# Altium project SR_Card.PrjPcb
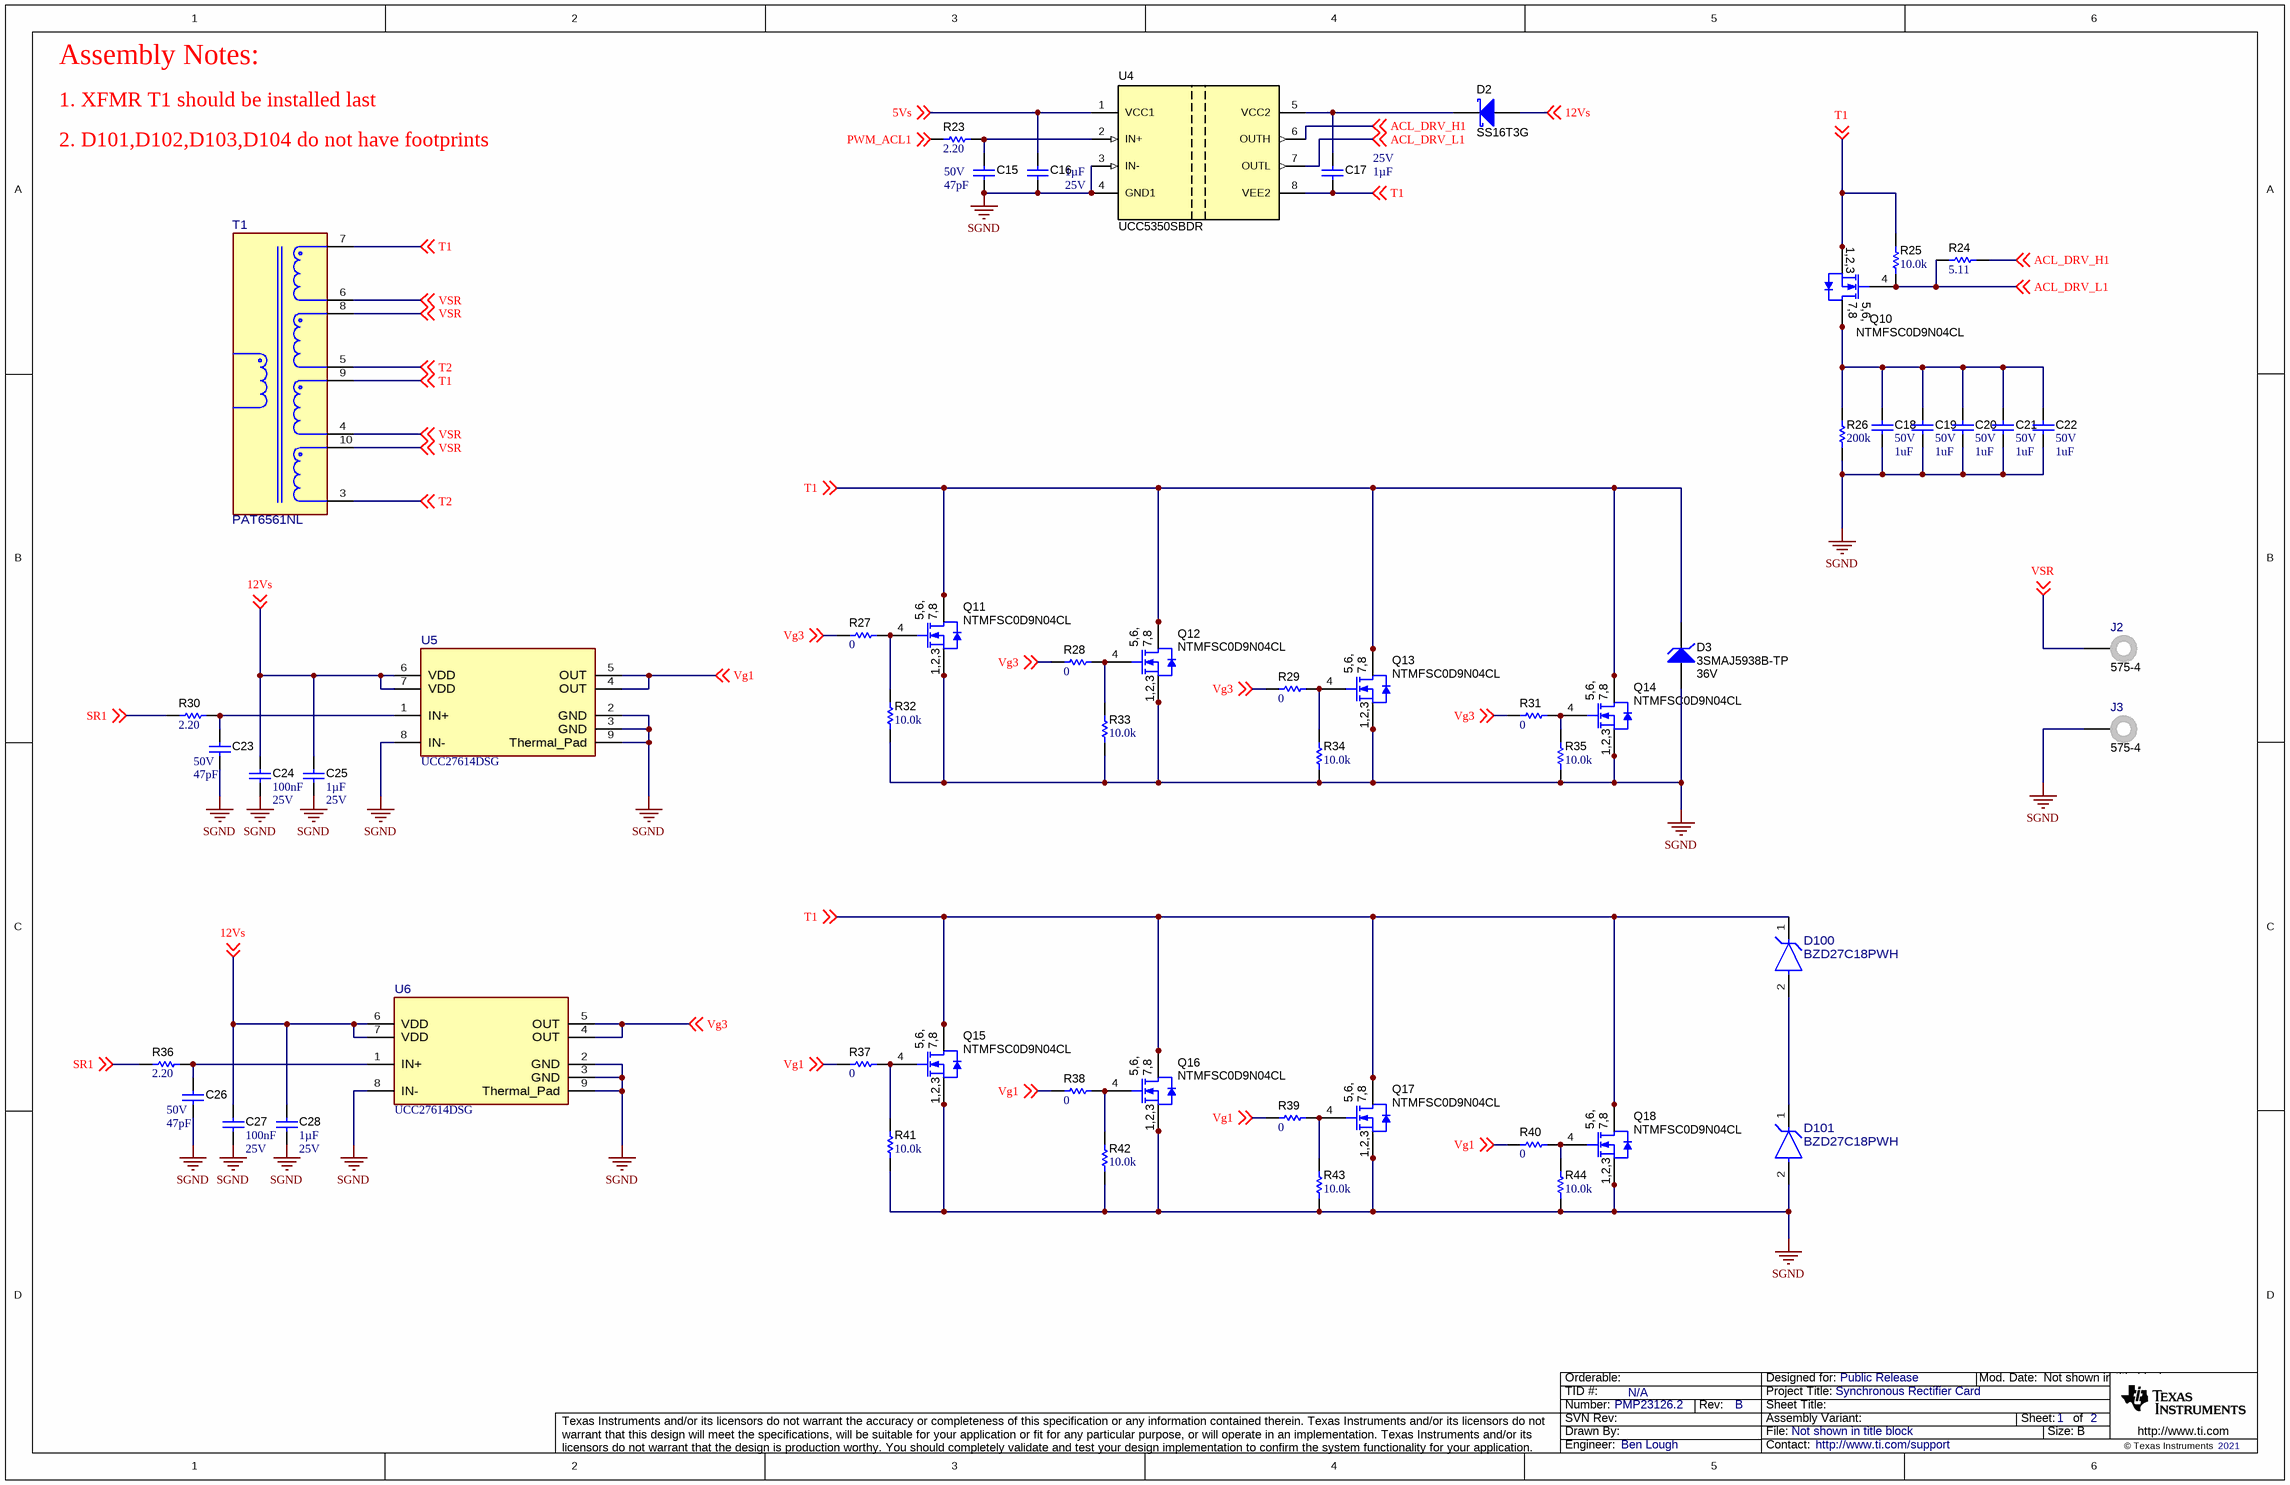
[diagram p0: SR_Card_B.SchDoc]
CopyrightYear: 2021; PCB_Layout: Ben Lough; PCB_Rev: B; PRJ_Customer: Public Release; PRJ_Engineer: Ben Lough; PRJ_Number: PMP23126.2; PRJ_Title: Synchronous Rectifier Card; SCH_Rev: B; TechSupport: http://www.ti.com/support; TID: N/A
2 sheets, 108 parts. Net scope: global (net labels, ports and power ports of the same name join across sheets).
Board file: SR_and_Transformer.PcbDoc
Sheets:
  SR_Card_B.SchDoc
  SR_Card_A.SchDoc

## Sheet SR_Card_B.SchDoc
size 431 x 279 mm; Date: Not shown in title block; ApprovedBy: Not shown in title block; CheckedBy: Not shown in title block; Author: Not shown in title block; CompanyName: Not shown in title block; Engineer: Not shown in title block; Organization: Not shown in title block; Address1: Not shown in title block; Address2: Not shown in title block; Address3: Not shown in title block; Address4: Not shown in title block; DocumentNumber: 2; Revision: Use project parameter SCH_Rev; SheetNumber: 1; SheetTotal: 2; PageSetup: Record=PageOptions¦CenterHorizontal=True¦CenterVertical=True¦PrintScale=1.00¦XCorrection=1.00¦YCorrection=1.00¦PrintKind=0¦BorderSize=5000000¦LeftOffset=0¦BottomOffset=0¦Orientation=2¦PaperLength=1000¦PaperWidth=1000¦Scale=100¦PaperSource=15¦PrintQuality=600¦MediaType=1¦DitherType=10¦PaperKind=Letter¦PrintScaleMode=1

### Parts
C15  VDC_V: 50V  ValueDisplayed: 47pF  [0603L]  (hidden comment: C0603C470J5GACTU)
C16  Cap_F: 1µF  VDC_V: 25V  [0603L]  (hidden comment: C0603C105K3RACTU)
C17  Cap_F: 1µF  VDC_V: 25V  [0603L]  (hidden comment: C0603C105K3RACTU)
C18  VDC_V: 50V  ValueDisplayed: 1uF  [1206L]  (hidden comment: GRM31MR71H105KA88L)
C19  VDC_V: 50V  ValueDisplayed: 1uF  [1206L]  (hidden comment: GRM31MR71H105KA88L)
C20  VDC_V: 50V  ValueDisplayed: 1uF  [1206L]  (hidden comment: GRM31MR71H105KA88L)
C21  VDC_V: 50V  ValueDisplayed: 1uF  [1206L]  (hidden comment: GRM31MR71H105KA88L)
C22  VDC_V: 50V  ValueDisplayed: 1uF  [1206L]  (hidden comment: GRM31MR71H105KA88L)
C23  VDC_V: 50V  ValueDisplayed: 47pF  [0402L]  (hidden comment: GRM1555C1H470FA01D)
C24  Cap_F: 100nF  VDC_V: 25V  [0603L]  (hidden comment: C0603C104K3RACTU)
C25  Cap_F: 1µF  VDC_V: 25V  [0603L]  (hidden comment: CGA3E1X7R1E105K080AC)
C26  VDC_V: 50V  ValueDisplayed: 47pF  [0402L]  (hidden comment: GRM1555C1H470FA01D)
C27  Cap_F: 100nF  VDC_V: 25V  [0603L]  (hidden comment: C0603C104K3RACTU)
C28  Cap_F: 1µF  VDC_V: 25V  [0603L]  (hidden comment: CGA3E1X7R1E105K080AC)
D2  SS16T3G  [SMA]
D3  3SMAJ5938B-TP  value 36V  [SMA]
D100  BZD27C18PWH  [FP-BZD27C18PWH_SOD-123W-MFG]
D101  BZD27C18PWH  [FP-BZD27C18PWH_SOD-123W-MFG]
J2  575-4  [Keystone_575-4]
J3  575-4  [Keystone_575-4]
Q10  NTMFSC0D9N04CL  [PG-TDSON-8]
Q11  NTMFSC0D9N04CL  [PG-TDSON-8]
Q12  NTMFSC0D9N04CL  [PG-TDSON-8]
Q13  NTMFSC0D9N04CL  [PG-TDSON-8]
Q14  NTMFSC0D9N04CL  [PG-TDSON-8]
Q15  NTMFSC0D9N04CL  [PG-TDSON-8]
Q16  NTMFSC0D9N04CL  [PG-TDSON-8]
Q17  NTMFSC0D9N04CL  [PG-TDSON-8]
Q18  NTMFSC0D9N04CL  [PG-TDSON-8]
R23  ValueDisplayed: 2.20  [0603L]  (hidden comment: ERJ-3RQF2R2V)
R24  ValueDisplayed: 5.11  [0603L]  (hidden comment: RC0603FR-075R11L)
R25  ValueDisplayed: 10.0k  [0402L]  (hidden comment: RC0402FR-0710KL)
R26  ValueDisplayed: 200k  [1206L]  (hidden comment: RC1206FR-07200KL)
R27  ValueDisplayed: 0  [0402L]  (hidden comment: RC0402JR-070RL)
R28  ValueDisplayed: 0  [0402L]  (hidden comment: RC0402JR-070RL)
R29  ValueDisplayed: 0  [0402L]  (hidden comment: RC0402JR-070RL)
R30  ValueDisplayed: 2.20  [0402L]  (hidden comment: RCS04022R20FKED)
R31  ValueDisplayed: 0  [0402S]  (hidden comment: RC0402JR-070RL)
R32  ValueDisplayed: 10.0k  [0402L]  (hidden comment: RT0402BRD0710KL)
R33  ValueDisplayed: 10.0k  [0402L]  (hidden comment: RT0402BRD0710KL)
R34  ValueDisplayed: 10.0k  [0402L]  (hidden comment: RT0402BRD0710KL)
R35  ValueDisplayed: 10.0k  [0402L]  (hidden comment: RT0402BRD0710KL)
R36  ValueDisplayed: 2.20  [0402L]  (hidden comment: RCS04022R20FKED)
R37  ValueDisplayed: 0  [0402L]  (hidden comment: RC0402JR-070RL)
R38  ValueDisplayed: 0  [0402L]  (hidden comment: RC0402JR-070RL)
R39  ValueDisplayed: 0  [0402L]  (hidden comment: RC0402JR-070RL)
R40  ValueDisplayed: 0  [0402L]  (hidden comment: RC0402JR-070RL)
R41  ValueDisplayed: 10.0k  [0402L]  (hidden comment: RT0402BRD0710KL)
R42  ValueDisplayed: 10.0k  [0402L]  (hidden comment: RT0402BRD0710KL)
R43  ValueDisplayed: 10.0k  [0402L]  (hidden comment: RT0402BRD0710KL)
R44  ValueDisplayed: 10.0k  [0402L]  (hidden comment: RT0402BRD0710KL)
T1  PAT6561NL  [FP-PAT6561NL_PTH_TRANSFORMER_40MM5_32MM5-MFG]
U4  UCC5350SBDR  [D0008B_HV]
U5  UCC27614DSG  [DSG0008A-MFG]
U6  UCC27614DSG  [DSG0008A-MFG]

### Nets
SGND: C15.2 C16.2 C18.2 C19.2 C20.2 C21.2 C22.2 C23.2 C24.2 C25.2 C26.2 C27.2 C28.2 D3.2(A) D101.2(Anode) J3.1 Q11.1(S) Q11.2(S) Q11.3(S) Q12.1(S) Q12.2(S) Q12.3(S) Q13.1(S) Q13.2(S) Q13.3(S) Q14.1(S) Q14.2(S) Q14.3(S) Q15.1(S) Q15.2(S) Q15.3(S) Q16.1(S) Q16.2(S) Q16.3(S) Q17.1(S) Q17.2(S) Q17.3(S) Q18.1(S) Q18.2(S) Q18.3(S) R26.1 R32.1 R33.1 R34.1 R35.1 R41.1 R42.1 R43.1 R44.1 U4.3(IN-) U4.4(GND1) U5.2(GND) U5.3(GND) U5.8(IN-) U5.9(Thermal_Pad) U6.2(GND) U6.3(GND) U6.8(IN-) U6.9(Thermal_Pad)
5Vs: C16.1 U4.1(VCC1) ; off-sheet 5Vs
12Vs: C24.1 C25.1 C27.1 C28.1 D2.2(A) U5.6(VDD) U5.7(VDD) U6.6(VDD) U6.7(VDD) ; off-sheet 12Vs
ACL_DRV_H1: R24.2 U4.6(OUTH) ; off-sheet ACL_DRV_H1
ACL_DRV_L1: Q10.4(G) R24.1 R25.1 U4.7(OUTL) ; off-sheet ACL_DRV_L1
PWM_ACL1: R23.1 ; off-sheet PWM_ACL1
SR1: R30.1 R36.1 ; off-sheet SR1
T1: C17.2 D3.1(K) D100.1(Cathode) Q10.1(S) Q10.2(S) Q10.3(S) Q11.5(D) Q11.6(D) Q11.7(D) Q11.8(D) Q11.9(D) Q12.5(D) Q12.6(D) Q12.7(D) Q12.8(D) Q12.9(D) Q13.5(D) Q13.6(D) Q13.7(D) Q13.8(D) Q13.9(D) Q14.5(D) Q14.6(D) Q14.7(D) Q14.8(D) Q14.9(D) Q15.5(D) Q15.6(D) Q15.7(D) Q15.8(D) Q15.9(D) Q16.5(D) Q16.6(D) Q16.7(D) Q16.8(D) Q16.9(D) Q17.5(D) Q17.6(D) Q17.7(D) Q17.8(D) Q17.9(D) Q18.5(D) Q18.6(D) Q18.7(D) Q18.8(D) Q18.9(D) R25.2 T1.7 T1.9 U4.8(VEE2) ; off-sheet T1
T2: T1.3 T1.5 ; off-sheet T2
Vg1: R37.1 R38.1 R39.1 R40.1 U5.4(OUT) U5.5(OUT) ; off-sheet Vg1
Vg3: R27.1 R28.1 R29.1 R31.1 U6.4(OUT) U6.5(OUT) ; off-sheet Vg3
VSR: J2.1 T1.4 T1.6 T1.8 T1.10 ; off-sheet VSR
NetC15_1: C15.1 R23.2 U4.2(IN+)
NetC17_1: C17.1 D2.1(K) U4.5(VCC2)
NetC18_1: C18.1 C19.1 C20.1 C21.1 C22.1 Q10.5(D) Q10.6(D) Q10.7(D) Q10.8(D) Q10.9(D) R26.2
NetC23_1: C23.1 R30.2 U5.1(IN+)
NetC26_1: C26.1 R36.2 U6.1(IN+)
NetD100_2: D100.2(Anode) D101.1(Cathode)
NetQ11_4: Q11.4(G) R27.2 R32.2
NetQ12_4: Q12.4(G) R28.2 R33.2
NetQ13_4: Q13.4(G) R29.2 R34.2
NetQ14_4: Q14.4(G) R31.2 R35.2
NetQ15_4: Q15.4(G) R37.2 R41.2
NetQ16_4: Q16.4(G) R38.2 R42.2
NetQ17_4: Q17.4(G) R39.2 R43.2
NetQ18_4: Q18.4(G) R40.2 R44.2

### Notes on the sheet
- Assembly Notes:
- 1. XFMR T1 should be installed last
- 2. D101,D102,D103,D104 do not have footprints

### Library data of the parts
C15 = CMP-0006939-4: CAP, CERM, 47 pF, 50 V, +/- 5%, C0G/NP0, 0603; Manufacturer: Kemet; TaMin_C: -55°C; Polarized: N; SizeAreaWB_mm2: 4.68; Value1: Unknown; U/M: EA; Value: 47pF; TaMax_C: 125°C; SizeZ_mm: 1; SizeX_mm: 1.6; SizeY_mm: 0.8; Cap_Case: 0603; SizeArea_mm2: 1.28; AEC Category: Q200
C16 C17 = CMP-0006867-4: CAP, CERM, 1 uF, 25 V, +/- 10%, X7R, 0603; Manufacturer: Kemet; TaMin_C: -55°C; Polarized: N; SizeAreaWB_mm2: 4.68; Value1: Unknown; U/M: EA; Value: 1uF; TaMax_C: 125°C; SizeZ_mm: 1; SizeX_mm: 1.6; SizeY_mm: 0.8; Cap_Case: 0603; SizeArea_mm2: 1.28; AEC Category: Q200
C18-C22 = CMP-0008992-2: CAP, CERM, 1 uF, 50 V, +/- 10%, X7R, 1206; Manufacturer: MuRata; TaMin_C: -55°C; Polarized: N; SizeAreaWB_mm2: 10.92; Value1: Unknown; U/M: EA; Value: 1uF; TaMax_C: 125°C; SizeZ_mm: 1.35; SizeX_mm: 3.2; SizeY_mm: 1.6; Cap_Case: 1206; SizeArea_mm2: 5.12; Cap_F: 1µF; AEC Category: Q200
C23 C26 = CMP-0006467-2: CAP, CERM, 47 pF, 50 V, +/- 1%, C0G/NP0, 0402; Manufacturer: MuRata; TaMin_C: -55°C; Polarized: N; SizeAreaWB_mm2: 3; Value1: Unknown; U/M: EA; Value: 47pF; TaMax_C: 125°C; SizeZ_mm: 0.6; SizeX_mm: 1; SizeY_mm: 0.5; Cap_Case: 0402; AEC Category: Q200
C24 C27 = CMP-0006859-4: CAP, CERM, 0.1 uF, 25 V, +/- 10%, X7R, 0603; Manufacturer: Kemet; TaMin_C: -55°C; Polarized: N; SizeAreaWB_mm2: 4.68; Value1: Unknown; U/M: EA; Value: 0.1uF; TaMax_C: 125°C; SizeZ_mm: 1; SizeX_mm: 1.6; SizeY_mm: 0.8; Cap_Case: 0603; SizeArea_mm2: 1.28; AEC Category: Q200
C25 C28 = CMP-0076705-3: CAP, CERM, 1 µF, 25 V,+/- 10%, X7R, AEC-Q200 Grade 1, 0603; Manufacturer: TDK; SizeAreaWB_mm2: 4.68; SizeArea_mm2: 1.28; AEC Qualified: Y; AEC Category: Q200; Value: 1uF; TaMax_C: 125°C; SizeZ_mm: 1.0; AEC Grade: 1; Polarized: N; TaMin_C: -55°C; SizeY_mm: 0.8; U/M: EA; SizeX_mm: 1.6; Cap_Case: 1.6x0.8x0.8mm
D2 = CMP-0028585-2: Diode, Schottky, 60 V, 1 A, SMA; Manufacturer: ON Semiconductor; Green_REACh: Incomplete; Value2: 0.72V; SizeArea_mm2: 16.3228; SizeZ_mm: 2.87; Io_A: 1A; Value: 60V; SizeX_mm: 5.59; Green_Lifecycle: Not Set; TJmax_C: 125°C; SizeAreaWB_mm2: 37.3428; RJC_CperW: 35; AEC Category: Q101; SizeY_mm: 2.92; Vf_V: 720mV
D3 = CMP-0005517-4: Diode, Zener, 36 V, 3 W, SMA; Manufacturer: Micro Commercial Components; SizeArea_mm2: 16.3228; RJA_CperW: 226; AEC Category: Q101; SizeAreaWB_mm2: 37.3428; Power_W: 3W; SizeY_mm: 2.92; SizeZ_mm: 2.87; SizeX_mm: 5.59
D100 D101 = CMP-0093684-1: Zener Diode Single 18V 5% 15Ohm 2300mW Automotive 2-Pin SOD-123W T/R; Manufacturer: Taiwan Semiconductor; Zener Impedance: 15Ω; Vf_V: 18.9V; AEC Grade: Grade 0; Power_W: 1W; SizeZ_mm: 1.02mm; TJmax_C: 175°C; Max Reverse Leakage Current: 1uA; Standoff Height: 0mm; AEC Qualified: Yes
J2 J3 = CMP-0055165-2: Standard Banana Jack, Uninsulated, 5.5mm; Manufacturer: Keystone; CT: TRUE; Green_REACh: Passed; CNHeader: FALSE; Green_Lifecycle: Active
Q10-Q18 = CMP-0000292-1: MOSFET, N-CH, 40 V, 313 A, DFN8 5x6; Alternate Manufacturer: None; Manufacturer: OnSemi; SizeZ_mm: 1.12; ChType: N; Value2: 63 nC; Value1: 0.001; VdsMax_V: 30V; SizeX_mm: 5.99; SizeY_mm: 4.9; Vgs_V: 20V; Value: 30V; Rdson45_ohm: 1.8m; SizeArea_mm2: 29.351; AEC Category: Q101; IdsMax_A: 100A; SizeAreaWB_mm2: 55.131; U/M: EA; QgTyp_nC: 63
R23 = CMP-0022711-2: RES, 2.20, 1%, 0.1 W, 0603; Manufacturer: Panasonic; Power_W: 100mW; TempCo: 200 ppm/C; Value_Code: 2R20; U/M: EA; Value: 2.20; Res_ohm: 2.2; SizeX_mm: 1.6; SizeY_mm: 0.8; SizeZ_mm: 1; Value2: 0.1W; SizeArea_mm2: 1.28; AEC Category: Q200
R24 = CMP-0023206-5: RES, 5.11, 1%, 0.1 W, 0603; Manufacturer: Yageo; Power_W: 100mW; TempCo: 200 ppm/C; Value_Code: 5R11; Value: 5.11; EIA_Code: E96; SizeX_mm: 1.6; SizeY_mm: 0.8; SizeZ_mm: 1; Value2: 0.1W; SizeArea_mm2: 1.28; AEC Qualified: N; VDC_V: 75V; AEC Category: Q200; SizeAreaWB_mm2: 4.68
R25 = CMP-0078669-1: RES, 10.0 k, 1%, 0.063 W, 0402; Manufacturer: Yageo America; Power_W: 63mW; Green_Lifecycle: Active; TempCo: 100 ppm/C; Value_Code: 10k0; Green_REACh: Passed; Value: 10.0k; EIA_Code: E96; Res_ohm: 10k; SizeX_mm: 1; SizeY_mm: 0.5; SizeZ_mm: 0.6; Value2: 0.063W; AEC Qualified: N; AEC Category: Q200
R26 = CMP-0018060-2: RES, 200 k, 1%, 0.25 W, 1206; Manufacturer: Yageo America; Power_W: 250mW; TempCo: 100 ppm/C; U/M: EA; Value: 200k; EIA_Code: E96; SizeX_mm: 3.2; SizeY_mm: 1.6; SizeZ_mm: 1.35; Value2: 0.25W; SizeArea_mm2: 5.12; VDC_V: 200V; AEC Category: Q200
R27-R29 R31 R37-R40 = CMP-0027004-2: RES, 0, 5%, 0.063 W, 0402; Manufacturer: Yageo America; Power_W: 63mW; TempCo: 200 ppm/C; Value_Code: 0000; U/M: EA; Value: 0; EIA_Code: E24; SizeX_mm: 1; SizeY_mm: 0.5; SizeZ_mm: 0.6; Value2: 0.063W; VDC_V: 50V; AEC Category: Q200
R30 R36 = CMP-0026747-1: RES, 2.20, 1%, 0.2 W, 0402; Manufacturer: Vishay-Dale; Power_W: 200mW; TempCo: 100 ppm/C; Value_Code: 2R20; U/M: EA; Value: 2.20; Res_ohm: 2.2; SizeX_mm: 1; SizeY_mm: 0.5; SizeZ_mm: 0.6; Value2: 0.2W; AEC Qualified: N; AEC Category: Q200
R32-R35 R41-R44 = CMP-0065360-1: RES, 10.0 k, .1%, .0625 W, 0402; Manufacturer: Yageo America; Power_W: 62.5mW; TempCo: 25 ppm/C; Value_Code: 10k0; U/M: EA; Value: 10.0k; EIA_Code: E192; Tolerance_%: 0.1%; Res_ohm: 10k; SizeX_mm: 1.0; SizeY_mm: 0.5; SizeZ_mm: 0.6; Value2: .0625W; VDC_V: 50V; AEC Category: Q200
T1 = CMP-0093678-1: XFMR, PSFB, 3KW, EW39, TH; Manufacturer: Pulse; Rsec1_ohm: 500µ; Ind_H: 663µH; Voltage_Isolation_Vrms: 3kV; Ns1toNp: 24; DCR_ohm: 50m; SizeZ_mm: 30.5mm; AEC Qualified: No; Frequency_Fixed: 100kHz
U4 = CMP-0077706-1: 3-kVRMS Single-Channel Isolated Gate Drivers, D0008B (SOIC-8); Alternate Manufacturer: Texas Instruments; SizeAreaWB_mm2: 55.2; SizeZ_mm: 1.75; SizeX_mm: 6.0; SizeY_mm: 4.9; SizeArea_mm2: 29.4; CompType: IC; AEC Qualified: N; AEC Category: Q200
U5 U6 = CMP-0090339-1: Single Channel 30V 10A High Speed Low Side Gate Driver; Manufacturer: Texas Instruments; Nominal Supply Current: 175uA; Standoff Height: 0mm; Propagation Delay: 17ns; Rise Time: 7ns; TJmax_C: +150°C; Number Of Drivers: 1; Fall Time: 5ns; Output Voltage: 0-26V; AEC Qualified: No; Min Supply Voltage: 4.5V; SizeZ_mm: 0.8mm; Max Supply Voltage: 26V

## Sheet SR_Card_A.SchDoc
size 431 x 279 mm; Date: Not shown in title block; ApprovedBy: Not shown in title block; CheckedBy: Not shown in title block; Author: Not shown in title block; CompanyName: Not shown in title block; Engineer: Not shown in title block; Organization: Not shown in title block; Address1: Not shown in title block; Address2: Not shown in title block; Address3: Not shown in title block; Address4: Not shown in title block; DocumentNumber: 1; Revision: Use project parameter SCH_Rev; SheetNumber: 2; SheetTotal: 2; PageSetup: Record=PageOptions¦CenterHorizontal=True¦CenterVertical=True¦PrintScale=1.00¦XCorrection=1.00¦YCorrection=1.00¦PrintKind=0¦BorderSize=5000000¦LeftOffset=0¦BottomOffset=0¦Orientation=2¦PaperLength=1000¦PaperWidth=1000¦Scale=100¦PaperSource=15¦PrintQuality=600¦MediaType=1¦DitherType=10¦PaperKind=Letter¦PrintScaleMode=1
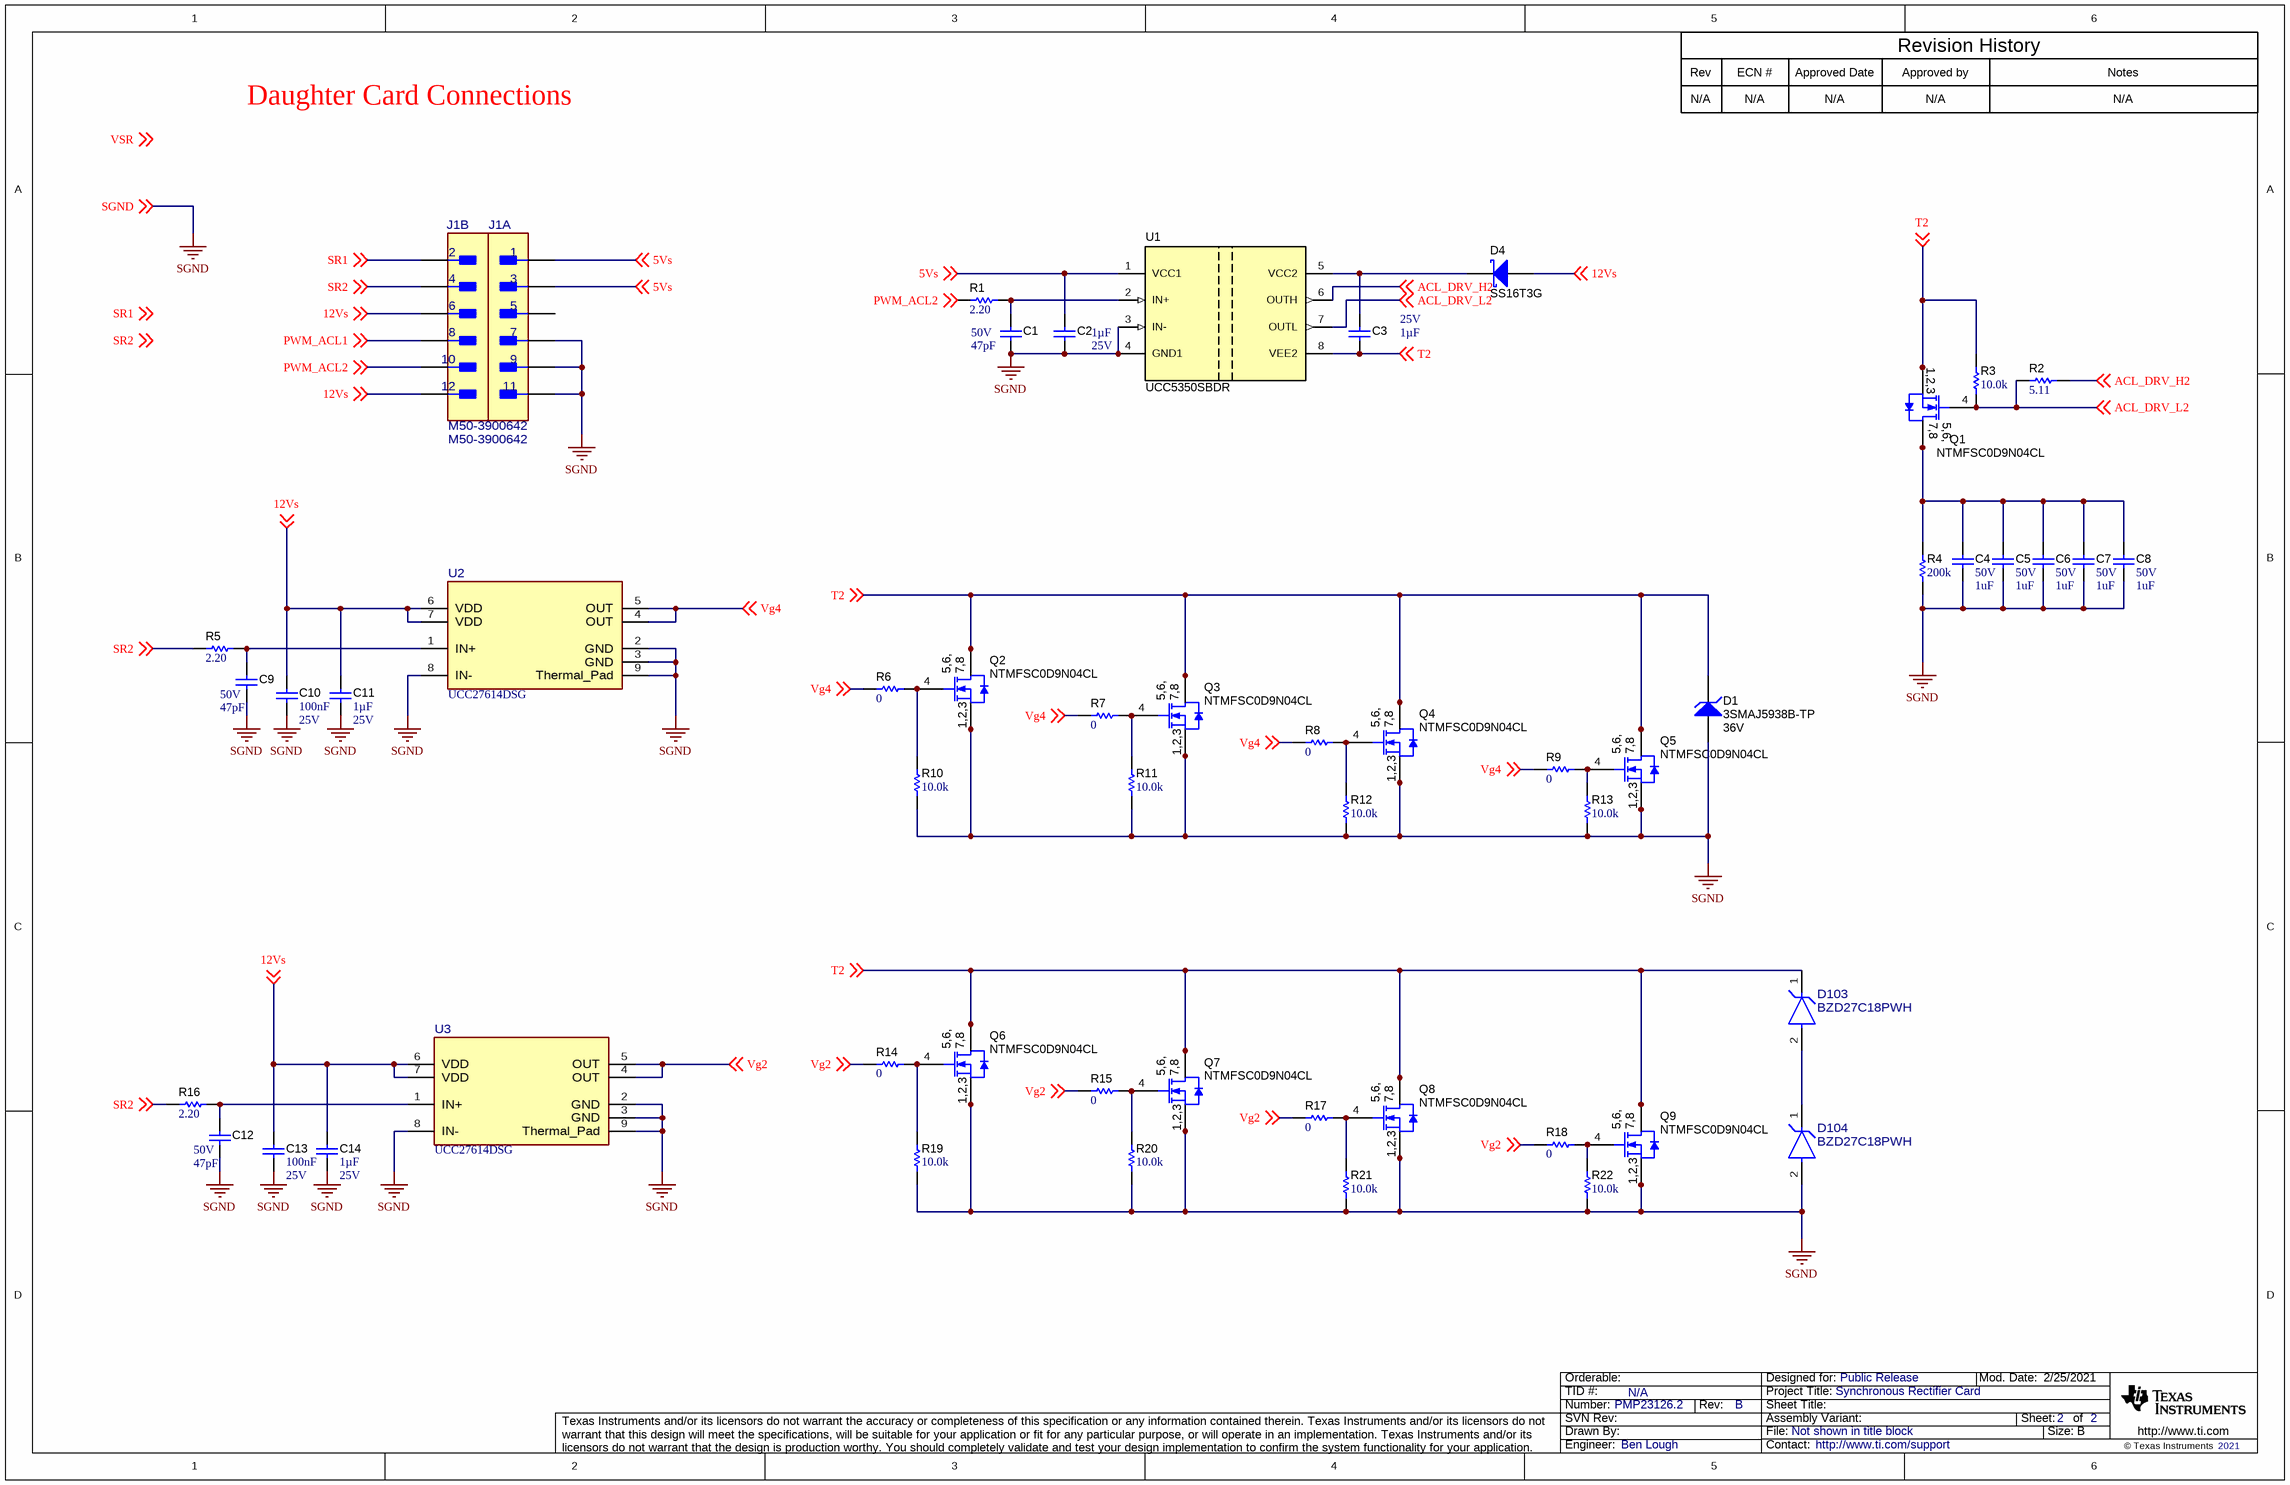
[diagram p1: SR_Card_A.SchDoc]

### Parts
C1  VDC_V: 50V  ValueDisplayed: 47pF  [0603L]  (hidden comment: C0603C470J5GACTU)
C2  Cap_F: 1µF  VDC_V: 25V  [0603L]  (hidden comment: C0603C105K3RACTU)
C3  Cap_F: 1µF  VDC_V: 25V  [0603L]  (hidden comment: C0603C105K3RACTU)
C4  VDC_V: 50V  ValueDisplayed: 1uF  [1206L]  (hidden comment: GRM31MR71H105KA88L)
C5  VDC_V: 50V  ValueDisplayed: 1uF  [1206L]  (hidden comment: GRM31MR71H105KA88L)
C6  VDC_V: 50V  ValueDisplayed: 1uF  [1206L]  (hidden comment: GRM31MR71H105KA88L)
C7  VDC_V: 50V  ValueDisplayed: 1uF  [1206L]  (hidden comment: GRM31MR71H105KA88L)
C8  VDC_V: 50V  ValueDisplayed: 1uF  [1206L]  (hidden comment: GRM31MR71H105KA88L)
C9  VDC_V: 50V  ValueDisplayed: 47pF  [0402L]  (hidden comment: GRM1555C1H470FA01D)
C10  Cap_F: 100nF  VDC_V: 25V  [0603L]  (hidden comment: C0603C104K3RACTU)
C11  Cap_F: 1µF  VDC_V: 25V  [0603L]  (hidden comment: CGA3E1X7R1E105K080AC)
C12  VDC_V: 50V  ValueDisplayed: 47pF  [0402L]  (hidden comment: GRM1555C1H470FA01D)
C13  Cap_F: 100nF  VDC_V: 25V  [0603L]  (hidden comment: C0603C104K3RACTU)
C14  Cap_F: 1µF  VDC_V: 25V  [0603L]  (hidden comment: CGA3E1X7R1E105K080AC)
D1  3SMAJ5938B-TP  value 36V  [SMA]
D4  SS16T3G  [SMA]
D103  BZD27C18PWH  [FP-BZD27C18PWH_SOD-123W-MFG]
D104  BZD27C18PWH  [FP-BZD27C18PWH_SOD-123W-MFG]
J1  M50-3900642  [FP-M50-3900642_HDR12-MFG]  (parts A,B of 2)
Q1  NTMFSC0D9N04CL  [PG-TDSON-8]
Q2  NTMFSC0D9N04CL  [PG-TDSON-8]
Q3  NTMFSC0D9N04CL  [PG-TDSON-8]
Q4  NTMFSC0D9N04CL  [PG-TDSON-8]
Q5  NTMFSC0D9N04CL  [PG-TDSON-8]
Q6  NTMFSC0D9N04CL  [PG-TDSON-8]
Q7  NTMFSC0D9N04CL  [PG-TDSON-8]
Q8  NTMFSC0D9N04CL  [PG-TDSON-8]
Q9  NTMFSC0D9N04CL  [PG-TDSON-8]
R1  ValueDisplayed: 2.20  [0603L]  (hidden comment: ERJ-3RQF2R2V)
R2  ValueDisplayed: 5.11  [0603L]  (hidden comment: RC0603FR-075R11L)
R3  ValueDisplayed: 10.0k  [0402L]  (hidden comment: RC0402FR-0710KL)
R4  ValueDisplayed: 200k  [1206L]  (hidden comment: RC1206FR-07200KL)
R5  ValueDisplayed: 2.20  [0402L]  (hidden comment: RCS04022R20FKED)
R6  ValueDisplayed: 0  [0402L]  (hidden comment: RC0402JR-070RL)
R7  ValueDisplayed: 0  [0402L]  (hidden comment: RC0402JR-070RL)
R8  ValueDisplayed: 0  [0402L]  (hidden comment: RC0402JR-070RL)
R9  ValueDisplayed: 0  [0402L]  (hidden comment: RC0402JR-070RL)
R10  ValueDisplayed: 10.0k  [0402L]  (hidden comment: RT0402BRD0710KL)
R11  ValueDisplayed: 10.0k  [0402L]  (hidden comment: RT0402BRD0710KL)
R12  ValueDisplayed: 10.0k  [0402L]  (hidden comment: RT0402BRD0710KL)
R13  ValueDisplayed: 10.0k  [0402L]  (hidden comment: RT0402BRD0710KL)
R14  ValueDisplayed: 0  [0402L]  (hidden comment: RC0402JR-070RL)
R15  ValueDisplayed: 0  [0402L]  (hidden comment: RC0402JR-070RL)
R16  ValueDisplayed: 2.20  [0402L]  (hidden comment: RCS04022R20FKED)
R17  ValueDisplayed: 0  [0402L]  (hidden comment: RC0402JR-070RL)
R18  ValueDisplayed: 0  [0402L]  (hidden comment: RC0402JR-070RL)
R19  ValueDisplayed: 10.0k  [0402L]  (hidden comment: RT0402BRD0710KL)
R20  ValueDisplayed: 10.0k  [0402L]  (hidden comment: RT0402BRD0710KL)
R21  ValueDisplayed: 10.0k  [0402L]  (hidden comment: RT0402BRD0710KL)
R22  ValueDisplayed: 10.0k  [0402L]  (hidden comment: RT0402BRD0710KL)
U1  UCC5350SBDR  [D0008B_HV]
U2  UCC27614DSG  [DSG0008A-MFG]
U3  UCC27614DSG  [DSG0008A-MFG]

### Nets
SGND: C1.2 C2.2 C4.2 C5.2 C6.2 C7.2 C8.2 C9.2 C10.2 C11.2 C12.2 C13.2 C14.2 D1.2(A) D104.2(Anode) J1.7 J1.9 J1.11 Q2.1(S) Q2.2(S) Q2.3(S) Q3.1(S) Q3.2(S) Q3.3(S) Q4.1(S) Q4.2(S) Q4.3(S) Q5.1(S) Q5.2(S) Q5.3(S) Q6.1(S) Q6.2(S) Q6.3(S) Q7.1(S) Q7.2(S) Q7.3(S) Q8.1(S) Q8.2(S) Q8.3(S) Q9.1(S) Q9.2(S) Q9.3(S) R4.1 R10.1 R11.1 R12.1 R13.1 R19.1 R20.1 R21.1 R22.1 U1.3(IN-) U1.4(GND1) U2.2(GND) U2.3(GND) U2.8(IN-) U2.9(Thermal_Pad) U3.2(GND) U3.3(GND) U3.8(IN-) U3.9(Thermal_Pad) ; off-sheet SGND
5Vs: C2.1 J1.1 J1.3 U1.1(VCC1) ; off-sheet 5Vs
12Vs: C10.1 C11.1 C13.1 C14.1 D4.2(A) J1.6 J1.12 U2.6(VDD) U2.7(VDD) U3.6(VDD) U3.7(VDD) ; off-sheet 12Vs
ACL_DRV_H2: R2.2 U1.6(OUTH) ; off-sheet ACL_DRV_H2
ACL_DRV_L2: Q1.4(G) R2.1 R3.1 U1.7(OUTL) ; off-sheet ACL_DRV_L2
PWM_ACL1: J1.8 ; off-sheet PWM_ACL1
PWM_ACL2: J1.10 R1.1 ; off-sheet PWM_ACL2
SR1: J1.2 ; off-sheet SR1
SR2: J1.4 R5.1 R16.1 ; off-sheet SR2
T2: C3.2 D1.1(K) D103.1(Cathode) Q1.1(S) Q1.2(S) Q1.3(S) Q2.5(D) Q2.6(D) Q2.7(D) Q2.8(D) Q2.9(D) Q3.5(D) Q3.6(D) Q3.7(D) Q3.8(D) Q3.9(D) Q4.5(D) Q4.6(D) Q4.7(D) Q4.8(D) Q4.9(D) Q5.5(D) Q5.6(D) Q5.7(D) Q5.8(D) Q5.9(D) Q6.5(D) Q6.6(D) Q6.7(D) Q6.8(D) Q6.9(D) Q7.5(D) Q7.6(D) Q7.7(D) Q7.8(D) Q7.9(D) Q8.5(D) Q8.6(D) Q8.7(D) Q8.8(D) Q8.9(D) Q9.5(D) Q9.6(D) Q9.7(D) Q9.8(D) Q9.9(D) R3.2 U1.8(VEE2) ; off-sheet T2
Vg2: R14.1 R15.1 R17.1 R18.1 U3.4(OUT) U3.5(OUT) ; off-sheet Vg2
Vg4: R6.1 R7.1 R8.1 R9.1 U2.4(OUT) U2.5(OUT) ; off-sheet Vg4
NetC1_1: C1.1 R1.2 U1.2(IN+)
NetC3_1: C3.1 D4.1(K) U1.5(VCC2)
NetC4_1: C4.1 C5.1 C6.1 C7.1 C8.1 Q1.5(D) Q1.6(D) Q1.7(D) Q1.8(D) Q1.9(D) R4.2
NetC9_1: C9.1 R5.2 U2.1(IN+)
NetC12_1: C12.1 R16.2 U3.1(IN+)
NetD103_2: D103.2(Anode) D104.1(Cathode)
NetQ2_4: Q2.4(G) R6.2 R10.2
NetQ3_4: Q3.4(G) R7.2 R11.2
NetQ4_4: Q4.4(G) R8.2 R12.2
NetQ5_4: Q5.4(G) R9.2 R13.2
NetQ6_4: Q6.4(G) R14.2 R19.2
NetQ7_4: Q7.4(G) R15.2 R20.2
NetQ8_4: Q8.4(G) R17.2 R21.2
NetQ9_4: Q9.4(G) R18.2 R22.2

Not connected (* = marked no-connect by the designer): J1 5

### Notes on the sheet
- Rev
- N/A
- ECN #
- Approved Date
- Approved by
- Revision History
- Notes
- Daughter Card Connections
- Labels drawn without touching a wire or pin: SR1, SR2, VSR

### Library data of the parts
C1 = CMP-0006939-4: as C15 on sheet SR_Card_B
C2 C3 = CMP-0006867-4: as C16 on sheet SR_Card_B
C4-C8 = CMP-0008992-2: as C18 on sheet SR_Card_B
C9 C12 = CMP-0006467-2: as C23 on sheet SR_Card_B
C10 C13 = CMP-0006859-4: as C24 on sheet SR_Card_B
C11 C14 = CMP-0076705-3: as C25 on sheet SR_Card_B
D1 = CMP-0005517-4: as D3 on sheet SR_Card_B
D4 = CMP-0028585-2: as D2 on sheet SR_Card_B
D103 D104 = CMP-0093684-1: as D100 on sheet SR_Card_B
J1 = CMP-0093439-1: Connector Header Through Hole, Right Angle 12 position 0.050" (1.27mm); Manufacturer: Harwin; Conn Gender: Male; Conn Orientation: Horizontal; ContactFinish: Gold,Nickel; Row_Count: 2; SizeZ_mm: 3.55mm; AEC Qualified: No; Current_A: 1A
Q1-Q9 = CMP-0000292-1: as Q10 on sheet SR_Card_B
R1 = CMP-0022711-2: as R23 on sheet SR_Card_B
R2 = CMP-0023206-5: as R24 on sheet SR_Card_B
R3 = CMP-0078669-1: as R25 on sheet SR_Card_B
R4 = CMP-0018060-2: as R26 on sheet SR_Card_B
R5 R16 = CMP-0026747-1: as R30 on sheet SR_Card_B
R6-R9 R14 R15 R17 R18 = CMP-0027004-2: as R27 on sheet SR_Card_B
R10-R13 R19-R22 = CMP-0065360-1: as R32 on sheet SR_Card_B
U1 = CMP-0077706-1: as U4 on sheet SR_Card_B
U2 U3 = CMP-0090339-1: as U5 on sheet SR_Card_B

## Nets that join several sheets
SGND: SR_Card_B (59 pins), SR_Card_A (61 pins)
5Vs: SR_Card_B (C16.1 U4.1), SR_Card_A (C2.1 J1.1 J1.3 U1.1)
12Vs: SR_Card_B (9 pins), SR_Card_A (11 pins)
PWM_ACL1: SR_Card_B (R23.1), SR_Card_A (J1.8)
SR1: SR_Card_B (R30.1 R36.1), SR_Card_A (J1.2)
T2: SR_Card_B (T1.3 T1.5), SR_Card_A (48 pins)

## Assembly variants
001: not fitted D1 D3 J2 J3 T1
